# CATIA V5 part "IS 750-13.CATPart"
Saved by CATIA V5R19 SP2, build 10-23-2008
Part number: IS 750-13
Bounding box of the stored display mesh (mm): x -24.865 to 24.865, y -24.997 to 24.997, z 0 to 120.4
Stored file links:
  C:\Users\Bora\Desktop\3D Katı model\IS serisi\IS 750\IS 750-13.CATPart
  C:\Program Files\Dassault Systemes\B19\intel_a\reffiles\standard\MetricThickPitch.txt
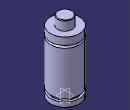
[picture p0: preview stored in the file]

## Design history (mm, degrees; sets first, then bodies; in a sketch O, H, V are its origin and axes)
Body1 (main body)
  Sketch1 on yz-plane, origin (0, 0, 0), H (0, 1, 0), V (0, 0, 1)
    point P3 (12.5, 119.4)
    point P5 (12.5, 119.4)
    point P10 (25, 87.9)
    point P11 (25, 91.9)
    point P13 (25, 91.9)
    point P14 (25, 87.9)
    line L1 (25, 0) -> (25, 8)
    line L2 (12.5, 119.4) -> (12.5, 104.4)
    arc A1 centre (11.5, 119.4) radius 1 from (12.5, 119.4) to (11.5, 120.4) ccw
    line L3 (21.5, 13) -> (21.5, 8)
    line L4 (25, 13) -> (25, 87.9)
    line L5 (25, 91.9) -> (25, 104.4)
    arc A2 centre (25, 89.9) radius 2 from (25, 91.9) to (25, 87.9) ccw
    line L6 (11.5, 120.4) -> (0, 120.4)
    point P15 (0, 120.4)
    line L7 (12.5, 104.4) -> (25, 104.4)
    line L8 (21.5, 13) -> (25, 13)
    line L9 (21.5, 8) -> (25, 8)
    line L10 (25, 0) -> (0, 0)
    coincidence: P15 V, P3 P5, P10 P14, P11 P13
    tangency: L6 A1
    horizontal: L7 H, L8 H, L9 H, L10 H
  Shaft1: profile Sketch1, axis Sketch1.V, angle 360
  Sketch2 on face of Shaft1 from Sketch1.L10, origin (0, 0, 0), H (1, 0, 0), V (0, -1, 0)
    point P1 (10, 0)
    distance P1 V = 10
  Hole1: placed by Sketch2, at (10, 0, 0) direction (0, 0, 1), diameter 6.647, depth 13, threaded "M8", thread diameter 8, thread depth 13, pitch 1.25
  Sketch3 on face of Shaft1 from Sketch1.L10, origin (0, 0, 0), H (1, 0, 0), V (0, -1, 0)
    point P1 (-10, 0)
    distance P1 V = 10
  Hole2: placed by Sketch3, at (-10, 0, 0) direction (0, 0, 1), diameter 6.647, depth 13, threaded "M8", thread diameter 8, thread depth 13, pitch 1.25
